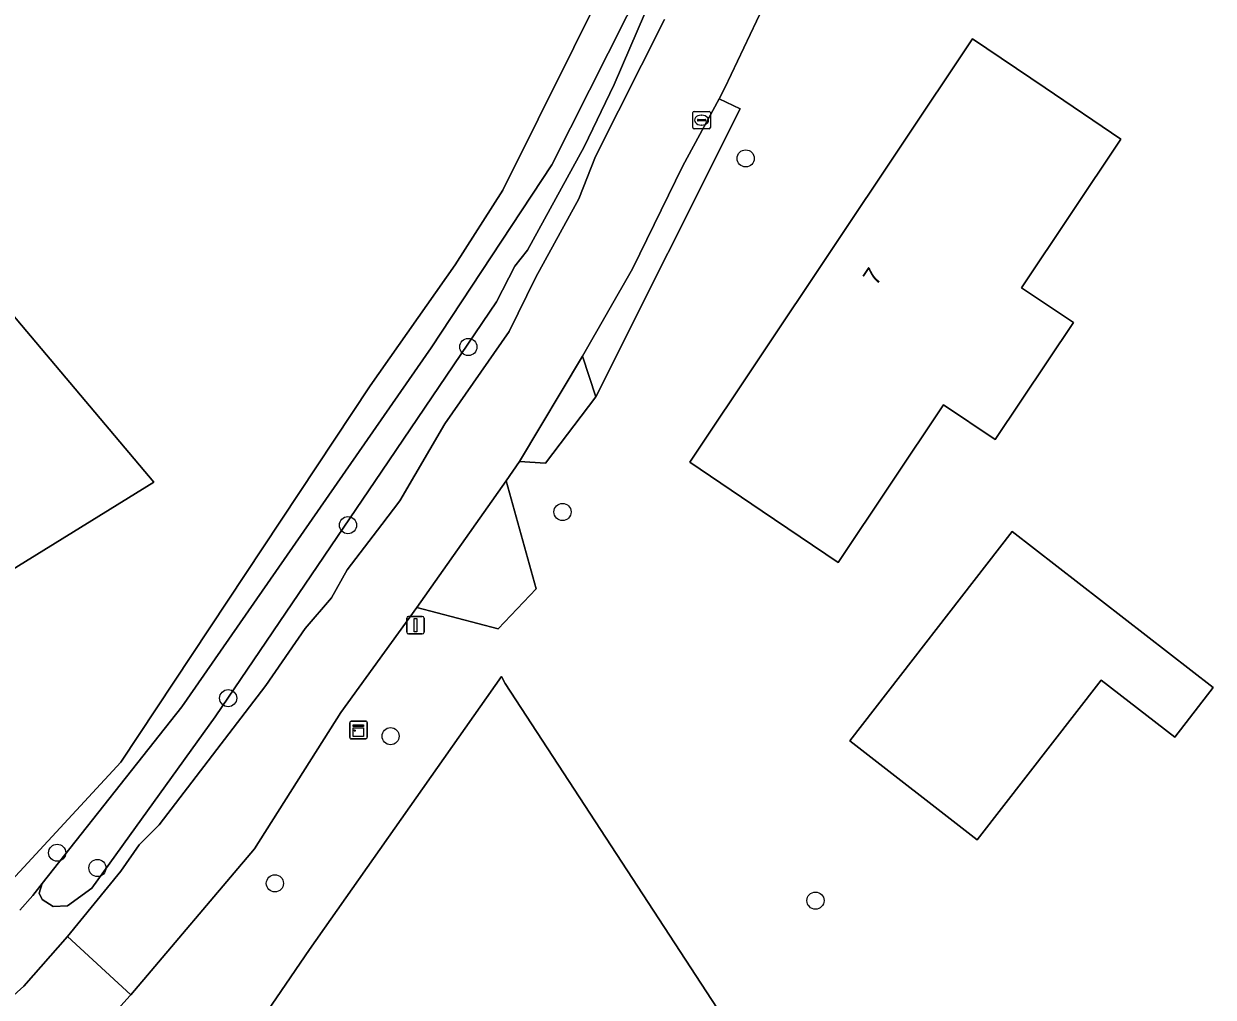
# Model space of a CAD drawing. Extents: x 164494 to 166241, y 382475 to 384495.
# Drawn here: x 164979.6 to 165047.4, y 382900.5 to 382956.1 of the extents above; entities that cross this region are included whole.
import ezdxf

# ---------------------------------------------------------------- set-up
doc = ezdxf.new("R2010")
doc.units = 0
for name, color, linetype in [('IMGEO_Boom', 7, 'Continuous'), ('IMGEO_Brandkraan', 7, 'Continuous'), ('IMGEO_Erf', 7, 'Continuous'), ('IMGEO_Grasland_agrarisch', 7, 'Continuous'), ('IMGEO_Grasland_overig', 7, 'Continuous'), ('IMGEO_Groenvoorziening', 7, 'Continuous'), ('IMGEO_Hek', 7, 'Continuous'), ('IMGEO_Kast', 7, 'Continuous'), ('IMGEO_Lichtmast', 7, 'Continuous'), ('IMGEO_Loofbos', 7, 'Continuous'), ('IMGEO_Pand', 7, 'Continuous'), ('IMGEO_Pand_nummerreeks', 7, 'Continuous'), ('IMGEO_Rijbaan_lokaal_gesloten', 7, 'Continuous'), ('IMGEO_Rijbaan_lokaal_open', 7, 'Continuous'), ('IMGEO_Voetpad_halfverhard', 7, 'Continuous'), ('IMGEO_Voetpad_open', 7, 'Continuous'), ('IMGEO_Waterloop', 7, 'Continuous')]:
    doc.layers.add(name, color=color, linetype=linetype)

msp = doc.modelspace()

# ---------------------------------------------------------------- linework, layer by layer
at = {"layer": 'IMGEO_Boom'}
for centre in [(165020.759, 382948.382), (165004.933, 382937.617), (165010.31, 382928.2), (164998.067, 382927.448), (164991.235, 382917.57), (165000.5, 382915.4), (164981.477, 382908.747), (164983.774, 382907.877), (164993.9, 382907), (165024.738, 382906.014)]:
    msp.add_circle(centre, 0.489, dxfattribs=at)
at = {"layer": 'IMGEO_Brandkraan'}
for p, q in [((165017.743, 382950.142), (165017.743, 382950.994)), ((165017.818, 382951.068), (165018.67, 382951.068)), ((165018.744, 382950.994), (165018.744, 382950.142)), ((165018.002, 382950.562), (165018.002, 382950.574)), ((165018.44, 382950.525), (165018.042, 382950.525)), ((165018.045, 382950.611), (165018.443, 382950.611)), ((165018.254, 382950.288), (165018.229, 382950.288)), ((165018.231, 382950.848), (165018.256, 382950.848)), ((165018.486, 382950.574), (165018.486, 382950.562)), ((165018.67, 382950.068), (165017.818, 382950.068))]:
    msp.add_line(p, q, dxfattribs=at)
for points in [[(165017.743, 382950.142), (165017.743, 382950.994)], [(165017.818, 382951.068), (165018.67, 382951.068)], [(165018.744, 382950.994), (165018.744, 382950.142)], [(165018.67, 382950.068), (165017.818, 382950.068)]]:
    msp.add_lwpolyline(points, dxfattribs=at)
for centre, radius, start, end in [((165017.82, 382950.992), 0.0765, 91.55205, 178.44795), ((165017.82, 382950.992), 0.0765, 91.55205, 178.44795), ((165018.668, 382950.992), 0.0765, 1.55205, 88.44795), ((165018.668, 382950.992), 0.0765, 1.55205, 88.44795), ((165018.042, 382950.571), 0.0403, 85.87752, 175.75265), ((165018.039, 382950.561), 0.0366, 178.93798, 274.71019), ((165018.443, 382950.568), 0.043, 264.86636, 352.45326), ((165018.447, 382950.573), 0.0386, 1.73085, 96.63898), ((165017.82, 382950.144), 0.0765, 181.55205, 268.44795), ((165017.82, 382950.144), 0.0765, 181.55205, 268.44795), ((165018.668, 382950.144), 0.0765, 271.55205, 358.44795), ((165018.668, 382950.144), 0.0765, 271.55205, 358.44795)]:
    msp.add_arc(centre, radius, start, end, dxfattribs=at)
for centre, major_axis, ratio, start_param, end_param in [((165018.23, 382950.568), (-0.387, 0.002), 0.722429, 4.712389, 7.853982), ((165018.255, 382950.568), (-0.39, 0.002), 0.717154, 1.570796, 4.712389)]:
    msp.add_ellipse(centre, major_axis=major_axis, ratio=ratio, start_param=start_param, end_param=end_param, dxfattribs=at)
at = {"layer": 'IMGEO_Erf'}
for points in [[(165022.83, 382959.286), (165019.573, 382952.406), (165019.24, 382951.789), (165020.443, 382951.217), (165012.213, 382934.776), (165009.333, 382930.99), (165007.863, 382931.089), (165007.102, 382929.984), (165008.811, 382923.808), (165006.645, 382921.521), (165001.996, 382922.741), (164997.666, 382916.757), (164992.742, 382908.964), (164985.682, 382900.629), (164985.65, 382900.59), (164983.525, 382898.26)], [(164991.283, 382896.514), (164995.872, 382903.225), (165006.822, 382918.809), (165007.043, 382918.399), (165019.128, 382899.871)]]:
    msp.add_lwpolyline(points, dxfattribs=at)
for points in [[(165036.5, 382941.001), (165039.462, 382939.024), (165035, 382932.341), (165032.038, 382934.319), (165026.028, 382925.318), (165021.707, 382928.238), (165017.563, 382931.037), (165033.699, 382955.202), (165037.843, 382952.403), (165042.164, 382949.483)], [(165045.238, 382915.346), (165041.045, 382918.601), (165033.966, 382909.479), (165026.692, 382915.135), (165035.967, 382927.086), (165047.431, 382918.172)]]:
    msp.add_lwpolyline(points, close=True, dxfattribs=at)
at = {"layer": 'IMGEO_Grasland_agrarisch'}
msp.add_lwpolyline([(164978.417, 382906.671), (164985.101, 382913.922), (164999.326, 382935.399), (165004.186, 382942.312), (165006.908, 382946.571), (165012.979, 382958.784), (165015.209, 382963.242), (165014.915, 382963.833), (165012.834, 382965.5), (165009.734, 382967.834), (165001.853, 382975.356), (165000, 382977.286), (164992.399, 382983.912), (164988.4, 382988.331), (164969.997, 382974.151)], dxfattribs=at)
for points in [[(164968.509, 382951.824), (164986.985, 382929.9), (164978.227, 382924.485), (164959.569, 382945.916)], [(165007.043, 382918.399), (165006.822, 382918.809), (164995.872, 382903.225), (164991.283, 382896.514), (164988.369, 382892.566), (164988.583, 382892.313), (165012.894, 382863.656), (165043.103, 382884.073), (165044.277, 382884.874), (165036.892, 382893.976), (165028.021, 382886.396), (165019.128, 382899.871)]]:
    msp.add_lwpolyline(points, close=True, dxfattribs=at)
at = {"layer": 'IMGEO_Grasland_overig'}
msp.add_lwpolyline([(164979.355, 382905.468), (164980.096, 382906.311), (164980.625, 382906.982), (164988.585, 382917.085), (165002.824, 382937.566), (165009.708, 382948.007), (165016.119, 382960.789), (165016.533, 382962.376), (165016.761, 382963.095), (165016.048, 382964.005), (165015.202, 382964.763), (165013.474, 382966.537), (165007.243, 382970.671), (165001.853, 382975.356), (165009.734, 382967.834), (165012.834, 382965.5), (165014.915, 382963.833), (165015.209, 382963.242), (165012.979, 382958.784), (165006.908, 382946.571), (165004.186, 382942.312), (164999.326, 382935.399), (164985.101, 382913.922), (164978.417, 382906.671)], dxfattribs=at)
at = {"layer": 'IMGEO_Groenvoorziening'}
for points in [[(165017.672, 382962.855), (165013.257, 382952.601), (165011.538, 382949.052), (165008.306, 382943.151), (165007.582, 382942.235), (165006.551, 382940.201), (165000, 382930.534), (164990.487, 382916.497), (164983.461, 382906.729), (164982.067, 382905.708), (164981.249, 382905.672), (164980.615, 382906.068), (164980.451, 382906.431), (164980.625, 382906.982), (164980.096, 382906.311), (164979.355, 382905.468)], [(164979.568, 382901.138), (164982.067, 382903.966), (164985.101, 382907.689), (164986.149, 382909.203), (164987.294, 382910.336), (164993.376, 382918.301), (164995.633, 382921.547), (164997.122, 382923.299), (164998.03, 382924.893), (165000, 382927.482), (165001.03, 382928.836), (165003.594, 382933.24), (165007.261, 382938.498), (165008.778, 382941.609), (165011.241, 382946.074), (165012.194, 382948.488), (165016.136, 382956.304)]]:
    msp.add_lwpolyline(points, dxfattribs=at)
at = {"layer": 'IMGEO_Hek'}
msp.add_lwpolyline([(164986.985, 382929.9), (164968.509, 382951.824)], dxfattribs=at)
at = {"layer": 'IMGEO_Kast'}
for p, q in [((164998.169, 382915.328), (164998.169, 382916.169)), ((164998.169, 382916.169), (164998.169, 382915.328)), ((164998.244, 382916.253), (164999.085, 382916.253)), ((164999.085, 382916.253), (164998.244, 382916.253)), ((164999.169, 382916.178), (164999.169, 382915.337)), ((164999.169, 382915.337), (164999.169, 382916.178)), ((164999.094, 382915.253), (164998.253, 382915.253)), ((164998.253, 382915.253), (164999.094, 382915.253))]:
    msp.add_line(p, q, dxfattribs=at)
for points in [[(164998.364, 382916.043), (164998.964, 382916.043), (164998.964, 382915.958), (164998.364, 382915.958), (164998.364, 382916.043)], [(164998.364, 382915.868), (164998.964, 382915.868), (164998.964, 382915.379), (164998.364, 382915.379), (164998.364, 382915.868)]]:
    msp.add_lwpolyline(points, dxfattribs=at)
msp.add_circle((164998.448, 382915.717), 0.0377, dxfattribs=at)
for centre, start, end in [((164998.247, 382916.175), 92.4484, 184.28452), ((164998.247, 382916.175), 92.4484, 184.28452), ((164999.091, 382916.175), 2.4484, 94.28452), ((164999.091, 382916.175), 2.4484, 94.28452), ((164998.247, 382915.331), 182.4484, 274.28452), ((164998.247, 382915.331), 182.4484, 274.28452), ((164999.091, 382915.331), 272.4484, 4.28452), ((164999.091, 382915.331), 272.4484, 4.28452)]:
    msp.add_arc(centre, 0.0779, start, end, dxfattribs=at)
at = {"layer": 'IMGEO_Lichtmast'}
for p, q in [((165001.419, 382921.338), (165001.419, 382922.138)), ((165001.419, 382922.138), (165001.419, 382921.338)), ((165001.519, 382922.238), (165002.309, 382922.238)), ((165002.309, 382922.238), (165001.519, 382922.238)), ((165002.409, 382922.138), (165002.409, 382921.338)), ((165002.409, 382921.338), (165002.409, 382922.138)), ((165002.309, 382921.238), (165001.519, 382921.238)), ((165001.519, 382921.238), (165002.309, 382921.238))]:
    msp.add_line(p, q, dxfattribs=at)
msp.add_lwpolyline([(165001.839, 382922.113), (165001.989, 382922.113), (165001.989, 382921.363), (165001.839, 382921.363), (165001.839, 382922.113)], dxfattribs=at)
for centre, start, end in [((165001.519, 382922.138), 90, 180), ((165001.519, 382922.138), 90, 180), ((165002.309, 382922.138), 0, 90), ((165002.309, 382922.138), 360, 90), ((165001.519, 382921.338), 180, 270), ((165001.519, 382921.338), 180, 270), ((165002.309, 382921.338), 270, 0), ((165002.309, 382921.338), 270, 0)]:
    msp.add_arc(centre, 0.1, start, end, dxfattribs=at)
at = {"layer": 'IMGEO_Loofbos'}
msp.add_lwpolyline([(164968.509, 382951.824), (164959.569, 382945.916), (164978.227, 382924.485), (164986.985, 382929.9)], close=True, dxfattribs=at)
at = {"layer": 'IMGEO_Pand'}
for points in [[(165036.5, 382941.001), (165042.164, 382949.483), (165037.843, 382952.403), (165033.699, 382955.202), (165017.563, 382931.037), (165021.707, 382928.238), (165026.028, 382925.318), (165032.038, 382934.319), (165035, 382932.341), (165039.462, 382939.024)], [(165045.238, 382915.346), (165047.431, 382918.172), (165035.967, 382927.086), (165026.692, 382915.135), (165033.966, 382909.479), (165041.045, 382918.601)]]:
    msp.add_lwpolyline(points, close=True, dxfattribs=at)
at = {"layer": 'IMGEO_Rijbaan_lokaal_gesloten'}
msp.add_lwpolyline([(165016.136, 382956.304), (165012.194, 382948.488), (165011.241, 382946.074), (165008.778, 382941.609), (165007.261, 382938.498), (165003.594, 382933.24), (165001.03, 382928.836), (165000, 382927.482), (164998.03, 382924.893), (164997.122, 382923.299), (164995.633, 382921.547), (164993.376, 382918.301), (164987.294, 382910.336), (164986.149, 382909.203), (164985.101, 382907.689), (164982.067, 382903.966), (164985.682, 382900.629), (164992.742, 382908.964), (164997.666, 382916.757), (165001.996, 382922.741), (165007.102, 382929.984), (165007.863, 382931.089), (165011.453, 382937.089), (165014.298, 382942.077), (165017.17, 382947.96), (165019.24, 382951.789), (165019.573, 382952.406), (165022.83, 382959.286)], dxfattribs=at)
at = {"layer": 'IMGEO_Rijbaan_lokaal_open'}
msp.add_lwpolyline([(164962.885, 382881.332), (164962.895, 382881.34), (164966.016, 382883.951), (164972.496, 382889.374), (164981.197, 382896.095), (164983.093, 382897.786), (164983.525, 382898.26), (164985.65, 382900.59), (164985.682, 382900.629), (164982.067, 382903.966), (164979.568, 382901.138), (164977.607, 382899.368), (164973.21, 382895.261), (164969.929, 382892.442), (164963.449, 382887.019), (164961.892, 382885.716), (164960.198, 382884.543), (164961.779, 382882.654)], close=True, dxfattribs=at)
at = {"layer": 'IMGEO_Voetpad_halfverhard'}
msp.add_lwpolyline([(165020.443, 382951.217), (165019.24, 382951.789), (165017.17, 382947.96), (165014.298, 382942.077), (165011.453, 382937.089), (165012.213, 382934.776)], close=True, dxfattribs=at)
at = {"layer": 'IMGEO_Voetpad_open'}
for points in [[(165012.213, 382934.776), (165011.453, 382937.089), (165007.863, 382931.089), (165009.333, 382930.99)], [(165007.102, 382929.984), (165001.996, 382922.741), (165006.645, 382921.521), (165008.811, 382923.808)]]:
    msp.add_lwpolyline(points, close=True, dxfattribs=at)
at = {"layer": 'IMGEO_Waterloop'}
msp.add_lwpolyline([(165016.119, 382960.789), (165009.708, 382948.007), (165002.824, 382937.566), (164988.585, 382917.085), (164980.625, 382906.982), (164980.451, 382906.431), (164980.615, 382906.068), (164981.249, 382905.672), (164982.067, 382905.708), (164983.461, 382906.729), (164990.487, 382916.497), (165000, 382930.534), (165006.551, 382940.201), (165007.582, 382942.235), (165008.306, 382943.151), (165011.538, 382949.052), (165013.257, 382952.601), (165017.672, 382962.855)], dxfattribs=at)

# ---------------------------------------------------------------- texts
at = {"layer": 'IMGEO_Pand_nummerreeks'}
msp.add_text('7', height=1, rotation=56.26446, dxfattribs=at).set_placement((165028.206, 382941.069))

doc.saveas('drawing.dxf')
